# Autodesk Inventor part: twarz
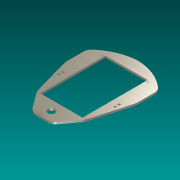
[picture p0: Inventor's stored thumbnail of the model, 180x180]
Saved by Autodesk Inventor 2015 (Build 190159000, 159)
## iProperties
Created: 2016-02
Part Number: twarz
Material: Generic
Document SubType Name: Modeling
Designer: Rafał
Density: 1 g/cm^3
Appearance: Light Beige
Author: Rafał
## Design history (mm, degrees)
sketch "Sketch1"
  geometry: L1 (0, 0)-(-107, 0); L2 (-107, 0)-(-107, 165); L3 (-107, 165)-(0, 165); L4 (0, 165)-(0, 0); L5 (-53.5, 0)-(-53.5, 165); L6 (-107, 82.5)-(0, 82.5); L7 (-53.5, 165)-(-53.5, 195); L8 (-53.5, 0)-(-53.5, -50); L9 (-53.5, 0)-(-53.5, 100); L10 (-53.5, 100)-(-143.5, 100); L11 (-53.5, 100)-(36.5, 100); L12 (-53.5, 0)-(-115.5, 0); L13 (-53.5, -50)-(-68.419, -50); L14 (-84.496, -41.897)-(-111.12, -5.918); L15 (-117.485, 7.09)-(-141.278, 92.064); L16 (-143.5, 108.242)-(-143.5, 146.423); L17 (36.5, 108.242)-(36.5, 146.423); L18 (10.485, 7.09)-(34.278, 92.064); L19 (-22.504, -41.897)-(4.12, -5.918); L20 (-53.5, -50)-(-38.581, -50); L21 (-127, 67.553)-(-122, 67.553); L22 (-122, 67.553)-(-122, 62.553); L23 (-122, 62.553)-(-127, 62.553); L24 (-127, 62.553)-(-127, 67.553); L25 (-127, 72.553)-(-122, 72.553); L26 (-122, 72.553)-(-122, 77.553); L27 (-122, 77.553)-(-127, 77.553); L28 (-127, 77.553)-(-127, 72.553); L29 (15, 72.553)-(15, 77.553); L30 (15, 77.553)-(20, 77.553); L31 (20, 77.553)-(20, 72.553); L32 (20, 72.553)-(15, 72.553); L33 (20, 67.553)-(15, 67.553); L34 (15, 67.553)-(15, 62.553); L35 (15, 62.553)-(20, 62.553); L36 (20, 62.553)-(20, 67.553); C1 r 1.75 at (4, 4); C2 r 1.75 at (-111, 4); C3 r 1.75 at (4, 161); C4 r 1.75 at (-111, 161); A1 r 134.263 centre (-47.771, 60.859) between (-53.5, 195) and (-136.755, 161.399); A2 r 20 centre (-123.5, 146.423) between (-136.755, 161.399) and (-143.5, 146.423); A3 r 20 centre (-68.419, -30) between (-84.496, -41.897) and (-68.419, -50); A4 r 40 centre (-78.967, 17.875) between (-117.485, 7.09) and (-111.12, -5.918); A5 r 60 centre (-83.5, 108.242) between (-143.5, 108.242) and (-141.278, 92.064); A6 r 134.263 centre (-59.229, 60.859) between (29.755, 161.399) and (-53.5, 195); A7 r 20 centre (16.5, 146.423) between (36.5, 146.423) and (29.755, 161.399); A8 r 60 centre (-23.5, 108.242) between (34.278, 92.064) and (36.5, 108.242); A9 r 40 centre (-28.033, 17.875) between (4.12, -5.918) and (10.485, 7.09); A10 r 20 centre (-38.581, -30) between (-38.581, -50) and (-22.504, -41.897); 2 further points
  constraints: 72 end point, 24 symmetric about line, 21 point on circle, 14 centre point, 9 point on line, 8 tangent, 7 perpendicular, 6 parallel, 4 horizontal, 4 midpoint, 1 vertical, 8 other
  dimensions: "d0" = 107 distance of L2.end L3.end; "d1" = 165 distance of L1.end L2.end; "d2" = 3.5 diameter of C1; "d3" = 4 distance from line of L4 C1.centre; "d4" = 4 distance from line of L1 C1.centre; "d5" = 30 distance of L5.end L7.end; "d6" = 50 distance of L5.start L8.end; "d7" = 100 distance of L5.start L9.end; "d8" = 90 distance of L9.end L10.end; "d9" = 90 distance of L9.end L11.end; "d10" = 62 distance of L5.start L12.end; "d11" = 25 distance of L8.end point (-78.5, -50); "d12" = 55 distance of L10.end point (-143.5, 155); "d13" = 20 radius of A2; "d14" = 20 radius of A3; "d15" = 40 radius of A4; "d16" = 60 radius of A5; "d19" = 5 distance of L22.end L23.end; "d20" = 5 distance of L21.end L22.end; "d21" = 15 distance between parallel lines of L2 L22; "d22" = 5 distance of L26.end L25.end; "d23" = 5 distance between parallel lines of L21 L25
extrude "Extrusion2" new body sketch "Sketch1" distance "d24" = 5; taper "d25" = 0 deg
sketch "Sketch2"
  geometry: L1 (0, 0)-(-107, 0) reference; L2 (-53.5, 0)-(-53.5, -50.11); C1 r 9 at (-53.5, -25.055)
  constraints: 2 end point, 2 midpoint, 1 centre point, 1 vertical
  dimensions: "d26" = 18 diameter of C1
extrude "Extrusion3" cut sketch "Sketch2" distance "d27" = 10; taper "d28" = 0 deg
body "Solid2"
